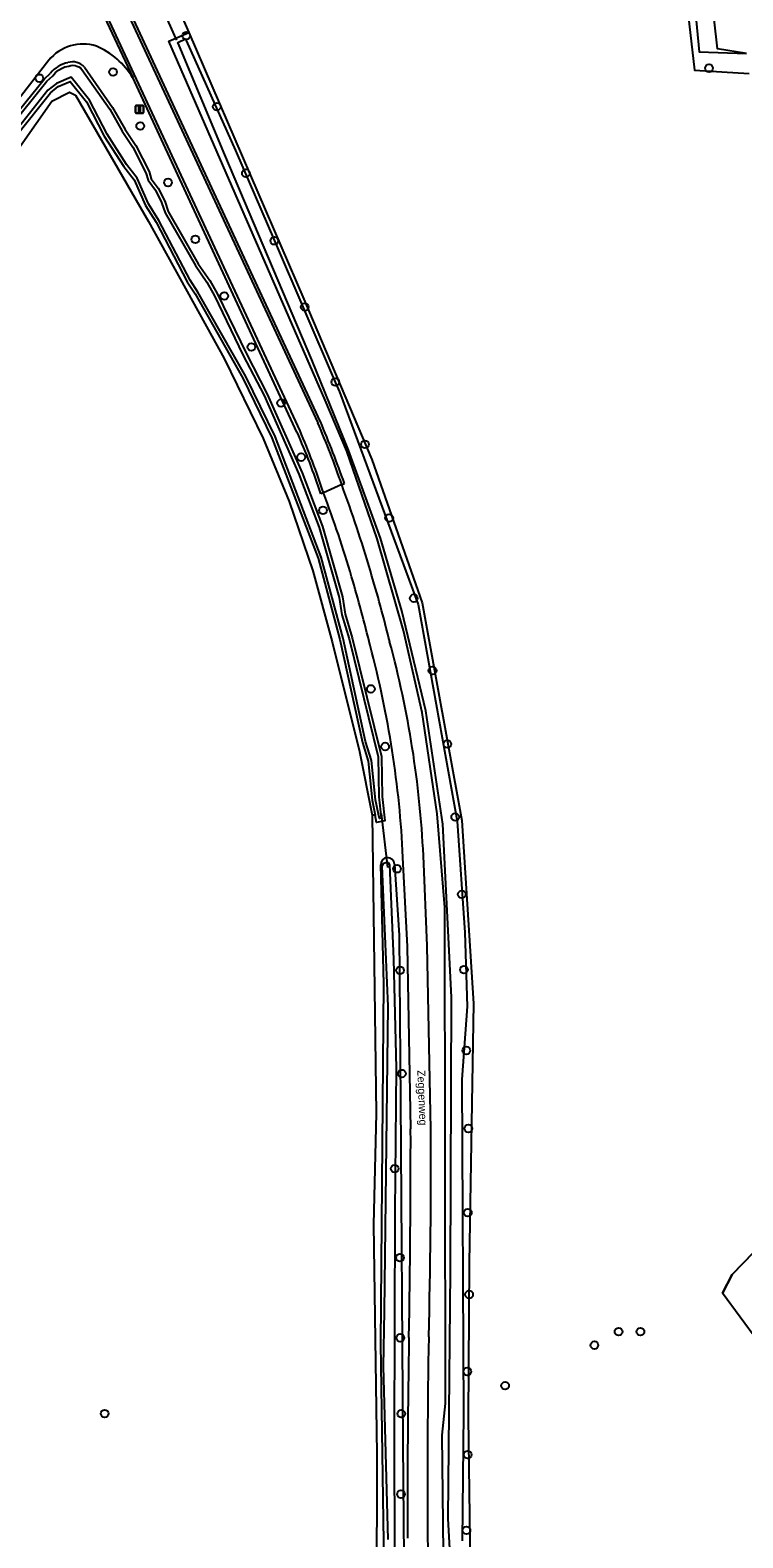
# Model space of a CAD drawing. Extents: x 164494 to 166241, y 382475 to 384494.
# Drawn here: x 165298.8 to 165388.9, y 383046.7 to 383237.3 of the extents above; entities that cross this region are included whole.
import ezdxf

# ---------------------------------------------------------------- set-up
doc = ezdxf.new("R2010")
doc.units = 0
for name, color, linetype in [('IMGEO_Boom', 7, 'Continuous'), ('IMGEO_Bouwland', 7, 'Continuous'), ('IMGEO_Duiker', 7, 'Continuous'), ('IMGEO_Grasland_agrarisch', 7, 'Continuous'), ('IMGEO_Grasland_overig', 7, 'Continuous'), ('IMGEO_Groenvoorziening', 7, 'Continuous'), ('IMGEO_Hek', 7, 'Continuous'), ('IMGEO_Loofbos', 7, 'Continuous'), ('IMGEO_Openbare_ruimte_label', 7, 'Continuous'), ('IMGEO_Rijbaan_lokaal_gesloten', 7, 'Continuous'), ('IMGEO_Rijbaan_lokaal_halfverhard', 7, 'Continuous'), ('IMGEO_Rijbaan_lokaal_open', 7, 'Continuous'), ('IMGEO_Verkeersbordpaal', 7, 'Continuous'), ('IMGEO_Waterloop', 7, 'Continuous')]:
    doc.layers.add(name, color=color, linetype=linetype)

msp = doc.modelspace()

# ---------------------------------------------------------------- linework, layer by layer
at = {"layer": 'IMGEO_Boom'}
for centre in [(165318.49, 383236.6), (165309.24, 383232.01), (165384.58, 383232.5), (165299.91, 383231.23), (165322.36, 383227.64), (165312.67, 383225.18), (165316.19, 383218.04), (165326.03, 383219.22), (165319.64, 383210.85), (165329.63, 383210.67), (165323.29, 383203.69), (165333.47, 383202.31), (165326.73, 383197.24), (165337.33, 383192.81), (165330.48, 383190.15), (165341.08, 383184.94), (165333.02, 383183.31), (165335.77, 383176.59), (165344.14, 383175.63), (165347.25, 383165.48), (165349.62, 383156.33), (165341.83, 383154.01), (165343.63, 383146.72), (165351.5, 383147.03), (165352.49, 383137.8), (165345.14, 383131.26), (165353.32, 383128.02), (165345.52, 383118.42), (165353.59, 383118.5), (165353.89, 383108.28), (165345.75, 383105.37), (165354.15, 383098.42), (165344.85, 383093.35), (165354.08, 383087.77), (165345.51, 383082.08), (165354.25, 383077.43), (165345.55, 383071.95), (165373.14, 383072.73), (165375.91, 383072.73), (165370.09, 383071.02), (165354.02, 383067.69), (165358.8, 383065.89), (165308.17, 383062.37), (165345.67, 383062.35), (165354.06, 383057.17), (165345.63, 383052.18), (165353.91, 383047.62)]:
    msp.add_circle(centre, 0.489, dxfattribs=at)
at = {"layer": 'IMGEO_Bouwland'}
msp.add_lwpolyline([(165232.93, 383146.62), (165236.73, 383150.93), (165255.21, 383169.77), (165268.73, 383184.22), (165282.44, 383201.21), (165301.48, 383228.34), (165303.71, 383229.45), (165304.49, 383229.08), (165313.7, 383213.1), (165323.27, 383195.77), (165328.23, 383185.67), (165331.48, 383177.72), (165334.48, 383168.92), (165336.93, 383159.97), (165340.39, 383146.11), (165341.99, 383138.03)], dxfattribs=at)
at = {"layer": 'IMGEO_Duiker'}
for points in [[(165317.3, 383236.06), (165317.19, 383236.3), (165314.24, 383242.95), (165314.17, 383243.11)], [(165343.13, 383138.24), (165343.95, 383131.44)]]:
    msp.add_lwpolyline(points, dxfattribs=at)
at = {"layer": 'IMGEO_Grasland_agrarisch'}
msp.add_lwpolyline([(165318.8, 383237.01), (165333.36, 383203.27), (165341.96, 383183.02), (165348.3, 383164.9), (165353.33, 383137.38), (165354.79, 383114.23), (165354.26, 383081.42), (165354.13, 383061.85), (165354.52, 383033.93), (165358.23, 383011.31), (165362.46, 382991.86), (165362.61, 382991.16), (165363.21, 382988.66), (165362.51, 382988.43)], dxfattribs=at)
at = {"layer": 'IMGEO_Grasland_overig'}
for points in [[(165371.97, 383334.46), (165373.42, 383327.31), (165374.59, 383314.12), (165378.54, 383270.12), (165379.79, 383257.89), (165382.73, 383232.25), (165389.65, 383231.83)], [(165389.32, 383234.36), (165385.65, 383234.96), (165383.95, 383250), (165382.16, 383265.72)], [(165315.92, 383243.68), (165318.8, 383237.01)], [(165362.51, 382988.43), (165360.31, 382987.73), (165352.99, 383023.83), (165352.05, 383031.27), (165351.91, 383033.04), (165351, 383044.75), (165350.84, 383059.66), (165351.27, 383063.65), (165351.16, 383126.38), (165350.22, 383138.2), (165348.33, 383151.01), (165345.95, 383161.38), (165342.61, 383173), (165338.81, 383184.07), (165336.06, 383190.51), (165316.3, 383235.92), (165317.19, 383236.3), (165318.8, 383237.01)], [(165305.61, 383232.63), (165309.18, 383227.54), (165310.75, 383224.76), (165312.11, 383222.71), (165313.8, 383219.43), (165314.06, 383218.51), (165314.96, 383217.31), (165315.77, 383215.68), (165316.21, 383214.38), (165320.01, 383207.77), (165321.47, 383205.67), (165322.46, 383203.91), (165326.05, 383196.46), (165328.71, 383191.28), (165333.13, 383181.35), (165335.71, 383174.56), (165338.25, 383165.65), (165338.59, 383163.45), (165339.48, 383160.45), (165343.19, 383145.48), (165343.26, 383140.41), (165343.61, 383137.33), (165342.56, 383137.11), (165342.37, 383138.06)], [(165233.88, 383149.26), (165232.83, 383150.35), (165237.3, 383155.71), (165238.99, 383157.46), (165244.19, 383162.81), (165246.45, 383164.79), (165249.54, 383168.2), (165253.72, 383172.09), (165262.35, 383180.93), (165264.46, 383183.73), (165269.29, 383189.33), (165271.45, 383191.63), (165273.23, 383194.09), (165277.04, 383198.62), (165284.8, 383209.82), (165295.77, 383225.19), (165300.55, 383231.16), (165301.32, 383231.86)], [(165342.37, 383138.06), (165341.99, 383138.03)], [(165341.99, 383138.03), (165342.5, 383100.3), (165342.17, 383086.29), (165342.6, 383057.26), (165342.54, 383038.74)], [(165342.53, 383037.25), (165343.58, 383037.76), (165343.08, 383071.25), (165343.47, 383116.72), (165343.08, 383131.76)], [(165344.83, 383131.86), (165345.4, 383122.86), (165345.56, 383101.96), (165345.88, 383058.63), (165346.03, 383039.23), (165345.98, 383036.47), (165345.79, 383036.04), (165345.47, 383035.17), (165344.1, 383034.39)]]:
    msp.add_lwpolyline(points, dxfattribs=at)
for centre, radius, start, end in [((165304.19, 383229.58), 3.67, 100.3235, 141.6723), ((165304.15, 383231.36), 1.94, 40.9926, 108.5719), ((165343.95, 383131.8), 0.875, 3.96, 182.396)]:
    msp.add_arc(centre, radius, start, end, dxfattribs=at)
at = {"layer": 'IMGEO_Groenvoorziening'}
msp.add_lwpolyline([(165297.16, 383224.15), (165301.31, 383229.4), (165302.31, 383230.19), (165303.81, 383230.83), (165305.88, 383228.23), (165308.13, 383223.92), (165310.58, 383220.08), (165311.9, 383218.37), (165313.33, 383215.13), (165314.67, 383213.03), (165318.61, 383205.48), (165319.61, 383203.96), (165325.64, 383193.3), (165329.32, 383185.75), (165335.15, 383170.54), (165337.92, 383160.26), (165340.75, 383147.25), (165341.49, 383144.87), (165342, 383139.92), (165342.37, 383138.06)], dxfattribs=at)
at = {"layer": 'IMGEO_Hek'}
for points in [[(165374.59, 383314.12), (165378.54, 383270.12), (165381.87, 383250), (165383.35, 383234.58), (165389.32, 383234.36)], [(165408.8, 383085.59), (165401.34, 383084.12), (165390.19, 383082.76), (165387.52, 383079.94), (165386.27, 383077.59)]]:
    msp.add_lwpolyline(points, dxfattribs=at)
at = {"layer": 'IMGEO_Loofbos'}
msp.add_lwpolyline([(165395.21, 383065.44), (165386.27, 383077.59), (165387.52, 383079.94), (165390.19, 383082.76), (165401.34, 383084.12), (165408.8, 383085.59)], dxfattribs=at)
at = {"layer": 'IMGEO_Rijbaan_lokaal_gesloten'}
for points in [[(165332.87, 383186.66), (165306.81, 383242.76), (165303.64, 383249.34), (165303.33, 383250)], [(165305.85, 383250.5), (165305.97, 383250.25), (165306.09, 383250), (165309.02, 383243.84), (165335.11, 383187.65)], [(165338.14, 383179.86), (165335.85, 383178.78)], [(165349.4, 383098.29), (165348.95, 383121.5), (165348.48, 383132.92)], [(165346.86, 383098.36), (165346.45, 383121.45), (165345.89, 383132.7)]]:
    msp.add_lwpolyline(points, dxfattribs=at)
for centre, radius, start, end in [((165233.86, 383144.61), 107.57, 18.5219, 23.009), ((165244.83, 383148.12), 98.56, 18.7841, 23.6453), ((165176.74, 383119.71), 169.73, 16.5968, 20.3672), ((165157.23, 383113.74), 192.62, 16.6533, 20.078), ((165177.84, 383120.05), 168.57, 13.524, 16.5946), ((165158.99, 383114.25), 190.78, 13.8684, 16.658), ((165219.68, 383126.86), 126.34, 2.652, 14.9603), ((165221.25, 383126.73), 127.37, 2.7853, 15.1304), ((163990.15, 383096.3), 1356.71, 358.97389, 0.087), ((164553.38, 383092.95), 796.04, 358.49686, 0.38453), ((166511.88, 383050.68), 1165.43, 178.95182, 180.1988), ((166298.47, 383053.61), 949.5, 178.88608, 180.41941), ((165458.13, 383047.83), 109.14, 180.6168, 190.4039)]:
    msp.add_arc(centre, radius, start, end, dxfattribs=at)
at = {"layer": 'IMGEO_Rijbaan_lokaal_halfverhard'}
msp.add_lwpolyline([(165301.1, 383233.5), (165294.45, 383224.95), (165273.9, 383196.62), (165269.53, 383190.91), (165266.52, 383187.24), (165262.08, 383182.29), (165253.04, 383172.85), (165249.5, 383169.5), (165246.23, 383165.97), (165242.87, 383162.82), (165240.74, 383160.44), (165239.08, 383158.89), (165238.62, 383158.37), (165234.41, 383153.64), (165232.13, 383150.82), (165226.21, 383142.5), (165218.7, 383130.81), (165201.6, 383105.79), (165199.81, 383103.29)], dxfattribs=at)
for centre, radius, start, end in [((165305.46, 383229.86), 5.68, 72.7984, 140.147), ((165303.2, 383226.12), 9.97, 31.3374, 66.7406)]:
    msp.add_arc(centre, radius, start, end, dxfattribs=at)
at = {"layer": 'IMGEO_Rijbaan_lokaal_open'}
for points in [[(165299.66, 383256.53), (165302.92, 383250), (165303.32, 383249.17), (165306.49, 383242.59), (165311.72, 383231.31)], [(165335.45, 383187.79), (165309.39, 383244.02), (165306.54, 383250), (165306.37, 383250.34), (165306.21, 383250.69)], [(165332.49, 383186.47), (165311.72, 383231.31)], [(165335.85, 383178.78), (165335.49, 383178.67)], [(165338.14, 383179.86), (165338.49, 383179.99)]]:
    msp.add_lwpolyline(points, dxfattribs=at)
for centre, radius, start, end in [((165263.47, 383155.44), 75.68, 17.8792, 24.2116), ((165186.61, 383125.42), 161.39, 19.7647, 22.7378)]:
    msp.add_arc(centre, radius, start, end, dxfattribs=at)
at = {"layer": 'IMGEO_Verkeersbordpaal'}
for p, q in [((165312.09, 383226.89), (165312.09, 383227.69)), ((165312.09, 383227.69), (165312.09, 383226.89)), ((165312.19, 383227.79), (165312.98, 383227.79)), ((165312.98, 383227.79), (165312.19, 383227.79)), ((165312.98, 383226.79), (165312.19, 383226.79)), ((165312.19, 383226.79), (165312.98, 383226.79)), ((165313.08, 383227.69), (165313.08, 383226.89)), ((165313.08, 383226.89), (165313.08, 383227.69))]:
    msp.add_line(p, q, dxfattribs=at)
msp.add_lwpolyline([(165312.51, 383227.66), (165312.66, 383227.66), (165312.66, 383226.91), (165312.51, 383226.91), (165312.51, 383227.66)], dxfattribs=at)
for centre, start, end in [((165312.19, 383227.69), 90, 180), ((165312.19, 383227.69), 90, 180), ((165312.19, 383226.89), 180, 270), ((165312.19, 383226.89), 180, 270), ((165312.98, 383227.69), 0, 90), ((165312.98, 383227.69), 360, 90), ((165312.98, 383226.89), 270, 0), ((165312.98, 383226.89), 270, 0)]:
    msp.add_arc(centre, 0.1, start, end, dxfattribs=at)
at = {"layer": 'IMGEO_Waterloop'}
for points in [[(165352.68, 383029.16), (165351.58, 383049.11), (165351.9, 383080.44), (165352.02, 383115.04), (165350.92, 383136.92), (165348.77, 383151.23), (165345.74, 383163.87), (165343.05, 383173.06), (165339.01, 383184.18), (165334.37, 383195.63), (165323.35, 383221.55), (165317.59, 383235.36), (165317.42, 383235.75), (165318.39, 383236.2)], [(165318.39, 383236.2), (165318.49, 383235.99), (165324.73, 383222.08), (165329.63, 383210.67), (165337.33, 383192.81), (165337.85, 383191.58), (165347.8, 383164.66), (165352.74, 383137.29), (165353.71, 383123.21), (165353.99, 383113.86), (165353.32, 383104.6), (165353.55, 383062.4), (165353.39, 383046.28)], [(165296.11, 383224.93), (165300.87, 383230.86), (165301.62, 383231.55), (165301.97, 383231.93), (165302.33, 383232.23), (165302.73, 383232.47), (165303.16, 383232.65), (165303.64, 383232.77)], [(165303.64, 383232.77), (165303.92, 383232.84), (165304.17, 383232.86), (165304.43, 383232.84), (165304.67, 383232.77), (165304.9, 383232.66), (165305.11, 383232.52), (165305.29, 383232.35), (165308.82, 383227.31), (165310.39, 383224.53), (165311.74, 383222.49), (165313.4, 383219.27), (165313.67, 383218.32), (165314.59, 383217.08), (165315.37, 383215.52), (165315.82, 383214.21), (165319.65, 383207.54), (165321.1, 383205.44), (165322.08, 383203.71), (165325.66, 383196.27), (165328.32, 383191.09), (165332.73, 383181.18), (165335.31, 383174.42), (165337.83, 383165.56), (165338.17, 383163.36), (165339.07, 383160.34), (165342.76, 383145.43), (165342.83, 383140.38), (165343.14, 383137.67), (165342.9, 383137.62), (165342.79, 383138.15), (165342.43, 383139.98), (165341.91, 383144.95), (165341.17, 383147.36), (165338.34, 383160.36), (165335.55, 383170.67), (165329.72, 383185.92), (165326.02, 383193.5), (165319.97, 383204.18), (165318.98, 383205.7), (165315.04, 383213.24), (165313.71, 383215.33), (165312.27, 383218.59), (165310.94, 383220.32), (165308.51, 383224.14), (165306.25, 383228.46), (165303.95, 383231.35), (165302.09, 383230.57), (165301, 383229.7), (165296.82, 383224.4)], [(165344.01, 383046.46), (165343.43, 383068.33), (165343.57, 383075.34), (165344.02, 383113.9), (165343.27, 383131.61), (165343.45, 383131.97), (165343.73, 383132.04), (165343.87, 383132.04), (165344, 383132.04), (165344.19, 383131.76), (165344.67, 383119.82), (165345.01, 383106.04), (165344.87, 383087.83), (165344.77, 383059.51), (165344.8, 383044.45)]]:
    msp.add_lwpolyline(points, dxfattribs=at)

# ---------------------------------------------------------------- texts
at = {"layer": 'IMGEO_Openbare_ruimte_label'}
msp.add_text('Zeggenweg', height=1, rotation=272.2356, dxfattribs=at).set_placement((165347.7, 383105.78))

doc.saveas('drawing.dxf')
